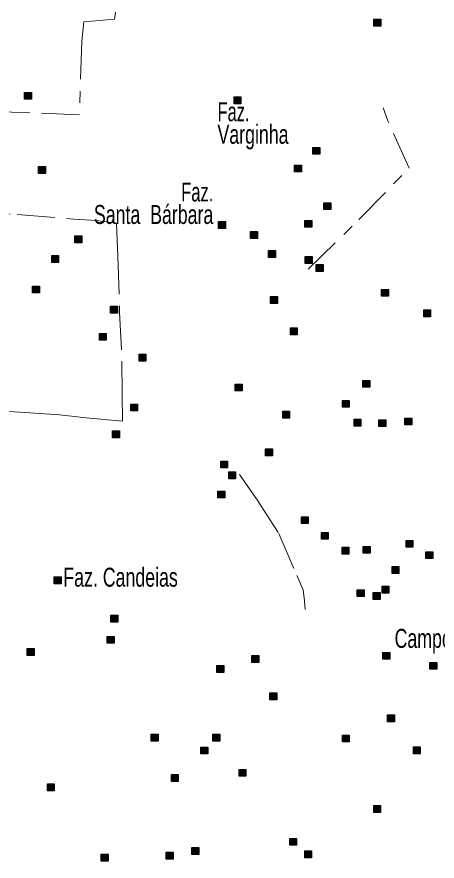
# Model space of a CAD drawing. Extents: x 445.6 to 500, y 8618.1 to 8673.4.
# Drawn here: x 473.87 to 477.42, y 8637.13 to 8644.26 of the extents above; entities that cross this region are included whole.
import ezdxf
from ezdxf.enums import TextEntityAlignment as Align

# ---------------------------------------------------------------- set-up
doc = ezdxf.new("R2010")
doc.units = 0
doc.header["$LTSCALE"] = 0.064
doc.linetypes.add('DOT_DASHED', pattern=[7.7, 5, -1.2, 0.3, -1.2])
doc.layers.add('2', color=7, linetype='Continuous', lineweight=25)
doc.layers.add('22', color=7, linetype='DOT_DASHED', lineweight=13)
doc.layers.add('61', color=7, linetype='Continuous')

msp = doc.modelspace()

# ---------------------------------------------------------------- hatches: boundary and pattern name
at = {"layer": '2'}
for points in [[(476.8858, 8644.2373), (476.9438, 8644.2373), (476.9438, 8644.1793), (476.8858, 8644.1793)], [(473.9393, 8643.62), (473.9973, 8643.62), (473.9973, 8643.562), (473.9393, 8643.562)], [(475.7068, 8643.583), (475.7648, 8643.583), (475.7648, 8643.525), (475.7068, 8643.525)], [(476.3722, 8643.1561), (476.4302, 8643.1561), (476.4302, 8643.0981), (476.3722, 8643.0981)], [(476.2168, 8643.007), (476.2748, 8643.007), (476.2748, 8642.949), (476.2168, 8642.949)], [(474.0575, 8642.9933), (474.1155, 8642.9933), (474.1155, 8642.9353), (474.0575, 8642.9353)], [(476.4655, 8642.6886), (476.5235, 8642.6886), (476.5235, 8642.6306), (476.4655, 8642.6306)], [(475.5751, 8642.5294), (475.6331, 8642.5294), (475.6331, 8642.4714), (475.5751, 8642.4714)], [(476.3047, 8642.5395), (476.3627, 8642.5395), (476.3627, 8642.4815), (476.3047, 8642.4815)], [(475.8453, 8642.4447), (475.9033, 8642.4447), (475.9033, 8642.3867), (475.8453, 8642.3867)], [(474.3638, 8642.4081), (474.4218, 8642.4081), (474.4218, 8642.3501), (474.3638, 8642.3501)], [(474.1676, 8642.2419), (474.2256, 8642.2419), (474.2256, 8642.1839), (474.1676, 8642.1839)], [(475.9973, 8642.2854), (476.0553, 8642.2854), (476.0553, 8642.2274), (475.9973, 8642.2274)], [(476.308, 8642.2346), (476.366, 8642.2346), (476.366, 8642.1766), (476.308, 8642.1766)], [(476.3992, 8642.1669), (476.4572, 8642.1669), (476.4572, 8642.1089), (476.3992, 8642.1089)], [(474.0059, 8641.9843), (474.0639, 8641.9843), (474.0639, 8641.9263), (474.0059, 8641.9263)], [(476.9506, 8641.9567), (477.0086, 8641.9567), (477.0086, 8641.8987), (476.9506, 8641.8987)], [(476.0144, 8641.8957), (476.0724, 8641.8957), (476.0724, 8641.8377), (476.0144, 8641.8377)], [(474.6653, 8641.8149), (474.7233, 8641.8149), (474.7233, 8641.7569), (474.6653, 8641.7569)], [(477.3076, 8641.7843), (477.3656, 8641.7843), (477.3656, 8641.7263), (477.3076, 8641.7263)], [(474.5707, 8641.5846), (474.6287, 8641.5846), (474.6287, 8641.5266), (474.5707, 8641.5266)], [(476.1819, 8641.632), (476.2399, 8641.632), (476.2399, 8641.574), (476.1819, 8641.574)], [(474.9051, 8641.4084), (474.9631, 8641.4084), (474.9631, 8641.3504), (474.9051, 8641.3504)], [(475.7157, 8641.1577), (475.7737, 8641.1577), (475.7737, 8641.0997), (475.7157, 8641.0997)], [(476.7942, 8641.188), (476.8522, 8641.188), (476.8522, 8641.13), (476.7942, 8641.13)], [(476.621, 8641.0188), (476.679, 8641.0188), (476.679, 8640.9608), (476.621, 8640.9608)], [(474.8342, 8640.9883), (474.8922, 8640.9883), (474.8922, 8640.9303), (474.8342, 8640.9303)], [(476.1177, 8640.9273), (476.1757, 8640.9273), (476.1757, 8640.8693), (476.1177, 8640.8693)], [(477.1488, 8640.8696), (477.2068, 8640.8696), (477.2068, 8640.8116), (477.1488, 8640.8116)], [(476.7189, 8640.8596), (476.7769, 8640.8596), (476.7769, 8640.8016), (476.7189, 8640.8016)], [(476.9293, 8640.856), (476.9873, 8640.856), (476.9873, 8640.798), (476.9293, 8640.798)], [(474.6822, 8640.7613), (474.7402, 8640.7613), (474.7402, 8640.7033), (474.6822, 8640.7033)], [(475.9725, 8640.6089), (476.0305, 8640.6089), (476.0305, 8640.5509), (475.9725, 8640.5509)], [(475.5941, 8640.5072), (475.6521, 8640.5072), (475.6521, 8640.4492), (475.5941, 8640.4492)], [(475.6617, 8640.4157), (475.7197, 8640.4157), (475.7197, 8640.3577), (475.6617, 8640.3577)], [(475.5705, 8640.2531), (475.6285, 8640.2531), (475.6285, 8640.1951), (475.5705, 8640.1951)], [(476.2751, 8640.0367), (476.3331, 8640.0367), (476.3331, 8639.9787), (476.2751, 8639.9787)], [(476.444, 8639.9041), (476.502, 8639.9041), (476.502, 8639.8461), (476.444, 8639.8461)], [(477.1579, 8639.8368), (477.2159, 8639.8368), (477.2159, 8639.7788), (477.1579, 8639.7788)], [(476.6175, 8639.7792), (476.6755, 8639.7792), (476.6755, 8639.7212), (476.6175, 8639.7212)], [(476.7965, 8639.786), (476.8545, 8639.786), (476.8545, 8639.728), (476.7965, 8639.728)], [(477.3256, 8639.7417), (477.3836, 8639.7417), (477.3836, 8639.6837), (477.3256, 8639.6837)], [(477.0397, 8639.6166), (477.0977, 8639.6166), (477.0977, 8639.5586), (477.0397, 8639.5586)], [(474.1885, 8639.5285), (474.2465, 8639.5285), (474.2465, 8639.4705), (474.1885, 8639.4705)], [(476.9553, 8639.4506), (477.0133, 8639.4506), (477.0133, 8639.3926), (476.9553, 8639.3926)], [(476.7459, 8639.4201), (476.8039, 8639.4201), (476.8039, 8639.3621), (476.7459, 8639.3621)], [(476.881, 8639.3964), (476.939, 8639.3964), (476.939, 8639.3384), (476.881, 8639.3384)], [(474.6668, 8639.2057), (474.7248, 8639.2057), (474.7248, 8639.1477), (474.6668, 8639.1477)], [(474.6364, 8639.0262), (474.6944, 8639.0262), (474.6944, 8638.9682), (474.6364, 8638.9682)], [(473.9616, 8638.9242), (474.0196, 8638.9242), (474.0196, 8638.8662), (473.9616, 8638.8662)], [(476.962, 8638.8916), (477.02, 8638.8916), (477.02, 8638.8336), (476.962, 8638.8336)], [(475.8575, 8638.8645), (475.9155, 8638.8645), (475.9155, 8638.8065), (475.8575, 8638.8065)], [(477.3589, 8638.8068), (477.4169, 8638.8068), (477.4169, 8638.7488), (477.3589, 8638.7488)], [(475.5618, 8638.7796), (475.6198, 8638.7796), (475.6198, 8638.7216), (475.5618, 8638.7216)], [(476.0095, 8638.5494), (476.0675, 8638.5494), (476.0675, 8638.4914), (476.0095, 8638.4914)], [(477.0013, 8638.3628), (477.0593, 8638.3628), (477.0593, 8638.3048), (477.0013, 8638.3048)], [(475.008, 8638.2004), (475.066, 8638.2004), (475.066, 8638.1424), (475.008, 8638.1424)], [(475.5281, 8638.2004), (475.5861, 8638.2004), (475.5861, 8638.1424), (475.5281, 8638.1424)], [(476.6209, 8638.1937), (476.6789, 8638.1937), (476.6789, 8638.1357), (476.6209, 8638.1357)], [(475.4268, 8638.092), (475.4848, 8638.092), (475.4848, 8638.034), (475.4268, 8638.034)], [(477.2204, 8638.0927), (477.2784, 8638.0927), (477.2784, 8638.0347), (477.2204, 8638.0347)], [(475.7492, 8637.9037), (475.8072, 8637.9037), (475.8072, 8637.8457), (475.7492, 8637.8457)], [(475.1776, 8637.8599), (475.2356, 8637.8599), (475.2356, 8637.8019), (475.1776, 8637.8019)], [(474.131, 8637.7814), (474.189, 8637.7814), (474.189, 8637.7234), (474.131, 8637.7234)], [(476.8848, 8637.598), (476.9428, 8637.598), (476.9428, 8637.54), (476.8848, 8637.54)], [(476.1759, 8637.3201), (476.2339, 8637.3201), (476.2339, 8637.2621), (476.1759, 8637.2621)], [(475.3502, 8637.2423), (475.4082, 8637.2423), (475.4082, 8637.1843), (475.3502, 8637.1843)], [(474.5855, 8637.1867), (474.6435, 8637.1867), (474.6435, 8637.1287), (474.5855, 8637.1287)], [(475.1341, 8637.2034), (475.1921, 8637.2034), (475.1921, 8637.1454), (475.1341, 8637.1454)], [(476.3034, 8637.2145), (476.3614, 8637.2145), (476.3614, 8637.1565), (476.3034, 8637.1565)]]:
    msp.add_hatch(color=256, dxfattribs=at).paths.add_polyline_path(points)

# ---------------------------------------------------------------- linework, layer by layer
for points in [[(476.8858, 8644.2373), (476.9438, 8644.2373), (476.9438, 8644.1793), (476.8858, 8644.1793)], [(473.9393, 8643.62), (473.9973, 8643.62), (473.9973, 8643.562), (473.9393, 8643.562)], [(475.7068, 8643.583), (475.7648, 8643.583), (475.7648, 8643.525), (475.7068, 8643.525)], [(476.3722, 8643.1561), (476.4302, 8643.1561), (476.4302, 8643.0981), (476.3722, 8643.0981)], [(476.2168, 8643.007), (476.2748, 8643.007), (476.2748, 8642.949), (476.2168, 8642.949)], [(474.0575, 8642.9933), (474.1155, 8642.9933), (474.1155, 8642.9353), (474.0575, 8642.9353)], [(476.4655, 8642.6886), (476.5235, 8642.6886), (476.5235, 8642.6306), (476.4655, 8642.6306)], [(475.5751, 8642.5294), (475.6331, 8642.5294), (475.6331, 8642.4714), (475.5751, 8642.4714)], [(476.3047, 8642.5395), (476.3627, 8642.5395), (476.3627, 8642.4815), (476.3047, 8642.4815)], [(475.8453, 8642.4447), (475.9033, 8642.4447), (475.9033, 8642.3867), (475.8453, 8642.3867)], [(474.3638, 8642.4081), (474.4218, 8642.4081), (474.4218, 8642.3501), (474.3638, 8642.3501)], [(474.1676, 8642.2419), (474.2256, 8642.2419), (474.2256, 8642.1839), (474.1676, 8642.1839)], [(475.9973, 8642.2854), (476.0553, 8642.2854), (476.0553, 8642.2274), (475.9973, 8642.2274)], [(476.308, 8642.2346), (476.366, 8642.2346), (476.366, 8642.1766), (476.308, 8642.1766)], [(476.3992, 8642.1669), (476.4572, 8642.1669), (476.4572, 8642.1089), (476.3992, 8642.1089)], [(474.0059, 8641.9843), (474.0639, 8641.9843), (474.0639, 8641.9263), (474.0059, 8641.9263)], [(476.9506, 8641.9567), (477.0086, 8641.9567), (477.0086, 8641.8987), (476.9506, 8641.8987)], [(476.0144, 8641.8957), (476.0724, 8641.8957), (476.0724, 8641.8377), (476.0144, 8641.8377)], [(474.6653, 8641.8149), (474.7233, 8641.8149), (474.7233, 8641.7569), (474.6653, 8641.7569)], [(477.3076, 8641.7843), (477.3656, 8641.7843), (477.3656, 8641.7263), (477.3076, 8641.7263)], [(474.5707, 8641.5846), (474.6287, 8641.5846), (474.6287, 8641.5266), (474.5707, 8641.5266)], [(476.1819, 8641.632), (476.2399, 8641.632), (476.2399, 8641.574), (476.1819, 8641.574)], [(474.9051, 8641.4084), (474.9631, 8641.4084), (474.9631, 8641.3504), (474.9051, 8641.3504)], [(475.7157, 8641.1577), (475.7737, 8641.1577), (475.7737, 8641.0997), (475.7157, 8641.0997)], [(476.7942, 8641.188), (476.8522, 8641.188), (476.8522, 8641.13), (476.7942, 8641.13)], [(476.621, 8641.0188), (476.679, 8641.0188), (476.679, 8640.9608), (476.621, 8640.9608)], [(474.8342, 8640.9883), (474.8922, 8640.9883), (474.8922, 8640.9303), (474.8342, 8640.9303)], [(476.1177, 8640.9273), (476.1757, 8640.9273), (476.1757, 8640.8693), (476.1177, 8640.8693)], [(477.1488, 8640.8696), (477.2068, 8640.8696), (477.2068, 8640.8116), (477.1488, 8640.8116)], [(476.7189, 8640.8596), (476.7769, 8640.8596), (476.7769, 8640.8016), (476.7189, 8640.8016)], [(476.9293, 8640.856), (476.9873, 8640.856), (476.9873, 8640.798), (476.9293, 8640.798)], [(474.6822, 8640.7613), (474.7402, 8640.7613), (474.7402, 8640.7033), (474.6822, 8640.7033)], [(475.9725, 8640.6089), (476.0305, 8640.6089), (476.0305, 8640.5509), (475.9725, 8640.5509)], [(475.5941, 8640.5072), (475.6521, 8640.5072), (475.6521, 8640.4492), (475.5941, 8640.4492)], [(475.6617, 8640.4157), (475.7197, 8640.4157), (475.7197, 8640.3577), (475.6617, 8640.3577)], [(475.5705, 8640.2531), (475.6285, 8640.2531), (475.6285, 8640.1951), (475.5705, 8640.1951)], [(476.2751, 8640.0367), (476.3331, 8640.0367), (476.3331, 8639.9787), (476.2751, 8639.9787)], [(476.444, 8639.9041), (476.502, 8639.9041), (476.502, 8639.8461), (476.444, 8639.8461)], [(477.1579, 8639.8368), (477.2159, 8639.8368), (477.2159, 8639.7788), (477.1579, 8639.7788)], [(476.6175, 8639.7792), (476.6755, 8639.7792), (476.6755, 8639.7212), (476.6175, 8639.7212)], [(476.7965, 8639.786), (476.8545, 8639.786), (476.8545, 8639.728), (476.7965, 8639.728)], [(477.3256, 8639.7417), (477.3836, 8639.7417), (477.3836, 8639.6837), (477.3256, 8639.6837)], [(477.0397, 8639.6166), (477.0977, 8639.6166), (477.0977, 8639.5586), (477.0397, 8639.5586)], [(474.1885, 8639.5285), (474.2465, 8639.5285), (474.2465, 8639.4705), (474.1885, 8639.4705)], [(476.9553, 8639.4506), (477.0133, 8639.4506), (477.0133, 8639.3926), (476.9553, 8639.3926)], [(476.7459, 8639.4201), (476.8039, 8639.4201), (476.8039, 8639.3621), (476.7459, 8639.3621)], [(476.881, 8639.3964), (476.939, 8639.3964), (476.939, 8639.3384), (476.881, 8639.3384)], [(474.6668, 8639.2057), (474.7248, 8639.2057), (474.7248, 8639.1477), (474.6668, 8639.1477)], [(474.6364, 8639.0262), (474.6944, 8639.0262), (474.6944, 8638.9682), (474.6364, 8638.9682)], [(473.9616, 8638.9242), (474.0196, 8638.9242), (474.0196, 8638.8662), (473.9616, 8638.8662)], [(476.962, 8638.8916), (477.02, 8638.8916), (477.02, 8638.8336), (476.962, 8638.8336)], [(475.8575, 8638.8645), (475.9155, 8638.8645), (475.9155, 8638.8065), (475.8575, 8638.8065)], [(477.3589, 8638.8068), (477.4169, 8638.8068), (477.4169, 8638.7488), (477.3589, 8638.7488)], [(475.5618, 8638.7796), (475.6198, 8638.7796), (475.6198, 8638.7216), (475.5618, 8638.7216)], [(476.0095, 8638.5494), (476.0675, 8638.5494), (476.0675, 8638.4914), (476.0095, 8638.4914)], [(477.0013, 8638.3628), (477.0593, 8638.3628), (477.0593, 8638.3048), (477.0013, 8638.3048)], [(475.008, 8638.2004), (475.066, 8638.2004), (475.066, 8638.1424), (475.008, 8638.1424)], [(475.5281, 8638.2004), (475.5861, 8638.2004), (475.5861, 8638.1424), (475.5281, 8638.1424)], [(476.6209, 8638.1937), (476.6789, 8638.1937), (476.6789, 8638.1357), (476.6209, 8638.1357)], [(475.4268, 8638.092), (475.4848, 8638.092), (475.4848, 8638.034), (475.4268, 8638.034)], [(477.2204, 8638.0927), (477.2784, 8638.0927), (477.2784, 8638.0347), (477.2204, 8638.0347)], [(475.7492, 8637.9037), (475.8072, 8637.9037), (475.8072, 8637.8457), (475.7492, 8637.8457)], [(475.1776, 8637.8599), (475.2356, 8637.8599), (475.2356, 8637.8019), (475.1776, 8637.8019)], [(474.131, 8637.7814), (474.189, 8637.7814), (474.189, 8637.7234), (474.131, 8637.7234)], [(476.8848, 8637.598), (476.9428, 8637.598), (476.9428, 8637.54), (476.8848, 8637.54)], [(476.1759, 8637.3201), (476.2339, 8637.3201), (476.2339, 8637.2621), (476.1759, 8637.2621)], [(475.3502, 8637.2423), (475.4082, 8637.2423), (475.4082, 8637.1843), (475.3502, 8637.1843)], [(474.5855, 8637.1867), (474.6435, 8637.1867), (474.6435, 8637.1287), (474.5855, 8637.1287)], [(475.1341, 8637.2034), (475.1921, 8637.2034), (475.1921, 8637.1454), (475.1341, 8637.1454)], [(476.3034, 8637.2145), (476.3614, 8637.2145), (476.3614, 8637.1565), (476.3034, 8637.1565)]]:
    msp.add_lwpolyline(points, close=True, dxfattribs=at)
at = {"layer": '22'}
for points in [[(474.7144, 8644.8659), (474.7052, 8644.2971), (474.6985, 8644.2399), (474.4392, 8644.2164), (474.4224, 8644.0516), (474.4019, 8643.4303), (473.9474, 8643.4505), (473.5029, 8643.4639), (472.8614, 8643.4942), (472.5348, 8643.5042), (472.082, 8643.5177), (471.752, 8643.5278), (471.651, 8643.5446), (471.6273, 8643.5448)], [(476.3325, 8642.1269), (476.7599, 8642.5469), (477.1836, 8642.9809), (477.0043, 8643.3803), (476.9654, 8643.4888)], [(472.2493, 8642.7048), (472.6821, 8642.6577), (473.2982, 8642.6216), (473.8754, 8642.5884), (474.3541, 8642.5496), (474.5456, 8642.5385), (474.7149, 8642.5163), (474.726, 8642.2364), (474.7405, 8641.7652), (474.7599, 8641.3495), (474.7628, 8641.0739), (474.7655, 8640.8439), (474.4575, 8640.8717), (474.2327, 8640.8966), (473.9403, 8640.9181), (473.5601, 8640.9403), (473.2105, 8640.968), (472.8179, 8640.9983), (472.5626, 8641.0177), (472.4988, 8641.0176)], [(475.7514, 8640.3942), (475.9075, 8640.1723), (476.0844, 8639.8946), (476.2361, 8639.5412), (476.2907, 8639.4196), (476.3002, 8639.3281), (476.3055, 8639.2531)]]:
    msp.add_lwpolyline(points, dxfattribs=at)

# ---------------------------------------------------------------- texts
at = {"layer": '61'}
for s, width, p in [('Faz.', 0.65, (475.5669, 8643.3766)), ('Varginha', 0.7, (475.5669, 8643.1866)), ('Faz. Candeias', 0.7, (474.2661, 8639.4462))]:
    msp.add_text(s, height=0.16, dxfattribs=dict(at, width=width)).set_placement(p)
for s, width, p in [('Faz.', 0.65, (475.5314, 8642.6992)), ('Santa  Bárbara', 0.7, (475.5314, 8642.5092)), ('Campo Verde', 0.7, (477.9852, 8638.9297))]:
    msp.add_text(s, height=0.16, dxfattribs=dict(at, width=width)).set_placement(p, align=Align.RIGHT)

doc.saveas('drawing.dxf')
